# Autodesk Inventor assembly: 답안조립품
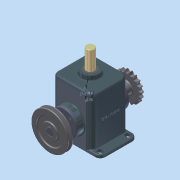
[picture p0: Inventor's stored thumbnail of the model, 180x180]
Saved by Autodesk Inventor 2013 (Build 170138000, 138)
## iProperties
Created: 2015-03
Part Number: 답안조립품
Document SubType Name: Assembly
Designer: Administrator
Mass: 8579.28 g
Surface Area: 4386.42 cm^2
Volume: 1982.54 cm^3
Density: 4.32742 g/cm^3
Author: Administrator
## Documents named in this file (15)
- C:\Documents and Settings\Administrator\바탕 화면\350305V1011\답안조립품.iam
- C:\Documents and Settings\Administrator\바탕 화면\350305V1011\본체.ipt
- C:\Documents and Settings\Administrator\바탕 화면\350305V1011\커버.ipt
- C:\Documents and Settings\Administrator\바탕 화면\350305V1011\베어링 6205.ipt
- C:\Documents and Settings\Administrator\바탕 화면\350305V1011\M4x0.5.ipt
- C:\Documents and Settings\Administrator\바탕 화면\350305V1011\오일실.ipt
- C:\Documents and Settings\Administrator\바탕 화면\350305V1011\편심축.ipt
- C:\Documents and Settings\Administrator\바탕 화면\350305V1011\멈춤링.ipt
- C:\Documents and Settings\Administrator\바탕 화면\350305V1011\키 8x8.ipt
- C:\Documents and Settings\Administrator\바탕 화면\350305V1011\체인 스프로킷.ipt
- C:\Documents and Settings\Administrator\바탕 화면\350305V1011\멈춤나사 M5x0.5.ipt
- C:\Documents and Settings\Administrator\바탕 화면\350305V1011\V-벨트풀리.ipt
- C:\Documents and Settings\Administrator\바탕 화면\350305V1011\부시.ipt
- C:\Documents and Settings\Administrator\바탕 화면\350305V1011\슬라이드.ipt
- C:\Documents and Settings\Administrator\바탕 화면\350305V1011\7-가변스프링.ipt
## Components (9 placed, 4 different names)
1. 5-체인 스프로킷:1 — 플러쉬:1, 각도:2
2. V-벨트풀리:1 — 플러쉬:2, 각도:4
3. 7-가변스프링:1
4. M4x0.5:1
5. M4x0.5:2
6. M4x0.5:3
7. M4x0.5:4
8. M4x0.5:5
9. M4x0.5:6
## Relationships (4: Flush 2, Angle 2)
- 플러쉬:1 [Flush]: 5-체인 스프로킷:1
- 각도:2 [Angle]: 5-체인 스프로킷:1
- 플러쉬:2 [Flush]: V-벨트풀리:1
- 각도:4 [Angle]: V-벨트풀리:1
